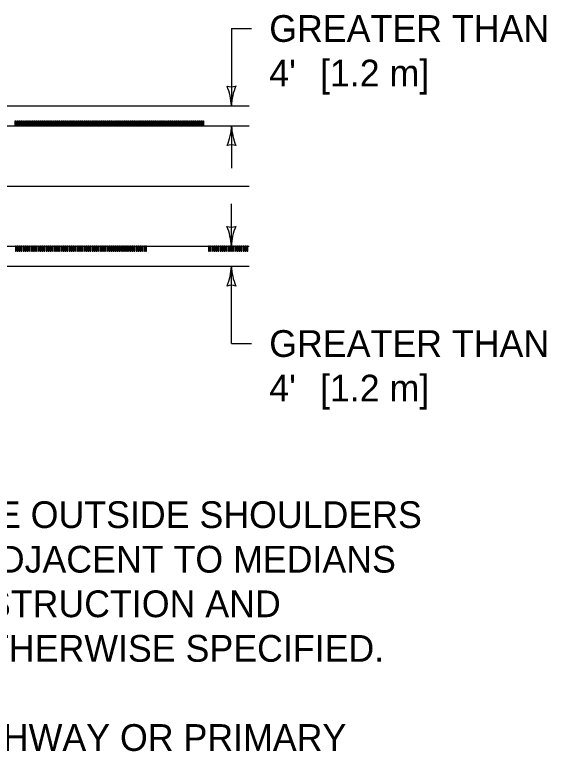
# Model space of a CAD drawing. Extents: x 49991.4 to 50021, y 49987.6 to 50011.4.
# Drawn here: x 50011.188 to 50012.382, y 49993.071 to 49994.724 of the extents above; entities that cross this region are included whole.
import ezdxf

# ---------------------------------------------------------------- set-up
doc = ezdxf.new("R2010")
doc.units = 0
for name, color, linetype in [('Level 1', 7, 'Continuous'), ('Level 2', 7, 'Continuous'), ('Level 3', 7, 'Continuous')]:
    doc.layers.add(name, color=color, linetype=linetype)

msp = doc.modelspace()

# ---------------------------------------------------------------- linework, layer by layer
at = {"layer": 'Level 1'}
for p, q in [((50005.3297, 49994.5195), (50011.7149, 49994.5195)), ((50005.3297, 49994.4745), (50011.7149, 49994.4745)), ((50005.3297, 49994.3395), (50011.7149, 49994.3395)), ((50005.3299, 49994.2045), (50011.7149, 49994.2045)), ((50007.8016, 49994.1595), (50011.7149, 49994.1595))]:
    msp.add_line(p, q, dxfattribs=at)
for points in [[(50011.1912, 49994.4745), (50011.1893, 49994.4745), (50011.1893, 49994.4857), (50011.1912, 49994.4857)], [(50011.1955, 49994.4745), (50011.1936, 49994.4745), (50011.1936, 49994.4857), (50011.1955, 49994.4857)], [(50011.1998, 49994.4745), (50011.1979, 49994.4745), (50011.1979, 49994.4857), (50011.1998, 49994.4857)], [(50011.2041, 49994.4745), (50011.2022, 49994.4745), (50011.2022, 49994.4857), (50011.2041, 49994.4857)], [(50011.2084, 49994.4745), (50011.2065, 49994.4745), (50011.2065, 49994.4857), (50011.2084, 49994.4857)], [(50011.2127, 49994.4745), (50011.2108, 49994.4745), (50011.2108, 49994.4857), (50011.2127, 49994.4857)], [(50011.217, 49994.4745), (50011.2151, 49994.4745), (50011.2151, 49994.4857), (50011.217, 49994.4857)], [(50011.2213, 49994.4745), (50011.2194, 49994.4745), (50011.2194, 49994.4857), (50011.2213, 49994.4857)], [(50011.2256, 49994.4745), (50011.2237, 49994.4745), (50011.2237, 49994.4857), (50011.2256, 49994.4857)], [(50011.2299, 49994.4745), (50011.228, 49994.4745), (50011.228, 49994.4857), (50011.2299, 49994.4857)], [(50011.2342, 49994.4745), (50011.2323, 49994.4745), (50011.2323, 49994.4857), (50011.2342, 49994.4857)], [(50011.2385, 49994.4745), (50011.2366, 49994.4745), (50011.2366, 49994.4857), (50011.2385, 49994.4857)], [(50011.2428, 49994.4745), (50011.2409, 49994.4745), (50011.2409, 49994.4857), (50011.2428, 49994.4857)], [(50011.2471, 49994.4745), (50011.2452, 49994.4745), (50011.2452, 49994.4857), (50011.2471, 49994.4857)], [(50011.2514, 49994.4745), (50011.2495, 49994.4745), (50011.2495, 49994.4857), (50011.2514, 49994.4857)], [(50011.2557, 49994.4745), (50011.2538, 49994.4745), (50011.2538, 49994.4857), (50011.2557, 49994.4857)], [(50011.26, 49994.4745), (50011.2581, 49994.4745), (50011.2581, 49994.4857), (50011.26, 49994.4857)], [(50011.2643, 49994.4745), (50011.2624, 49994.4745), (50011.2624, 49994.4857), (50011.2643, 49994.4857)], [(50011.2686, 49994.4745), (50011.2667, 49994.4745), (50011.2667, 49994.4857), (50011.2686, 49994.4857)], [(50011.2729, 49994.4745), (50011.271, 49994.4745), (50011.271, 49994.4857), (50011.2729, 49994.4857)], [(50011.2772, 49994.4745), (50011.2753, 49994.4745), (50011.2753, 49994.4857), (50011.2772, 49994.4857)], [(50011.2815, 49994.4745), (50011.2796, 49994.4745), (50011.2796, 49994.4857), (50011.2815, 49994.4857)], [(50011.2858, 49994.4745), (50011.2839, 49994.4745), (50011.2839, 49994.4857), (50011.2858, 49994.4857)], [(50011.2901, 49994.4745), (50011.2882, 49994.4745), (50011.2882, 49994.4857), (50011.2901, 49994.4857)], [(50011.2944, 49994.4745), (50011.2925, 49994.4745), (50011.2925, 49994.4857), (50011.2944, 49994.4857)], [(50011.2987, 49994.4745), (50011.2968, 49994.4745), (50011.2968, 49994.4857), (50011.2987, 49994.4857)], [(50011.303, 49994.4745), (50011.3011, 49994.4745), (50011.3011, 49994.4857), (50011.303, 49994.4857)], [(50011.3073, 49994.4745), (50011.3054, 49994.4745), (50011.3054, 49994.4857), (50011.3073, 49994.4857)], [(50011.3116, 49994.4745), (50011.3097, 49994.4745), (50011.3097, 49994.4857), (50011.3116, 49994.4857)], [(50011.3159, 49994.4745), (50011.314, 49994.4745), (50011.314, 49994.4857), (50011.3159, 49994.4857)], [(50011.3202, 49994.4745), (50011.3183, 49994.4745), (50011.3183, 49994.4857), (50011.3202, 49994.4857)], [(50011.3245, 49994.4745), (50011.3226, 49994.4745), (50011.3226, 49994.4857), (50011.3245, 49994.4857)], [(50011.3288, 49994.4745), (50011.3269, 49994.4745), (50011.3269, 49994.4857), (50011.3288, 49994.4857)], [(50011.3331, 49994.4745), (50011.3312, 49994.4745), (50011.3312, 49994.4857), (50011.3331, 49994.4857)], [(50011.3374, 49994.4745), (50011.3355, 49994.4745), (50011.3355, 49994.4857), (50011.3374, 49994.4857)], [(50011.3417, 49994.4745), (50011.3398, 49994.4745), (50011.3398, 49994.4857), (50011.3417, 49994.4857)], [(50011.346, 49994.4745), (50011.3441, 49994.4745), (50011.3441, 49994.4857), (50011.346, 49994.4857)], [(50011.3503, 49994.4745), (50011.3484, 49994.4745), (50011.3484, 49994.4857), (50011.3503, 49994.4857)], [(50011.3546, 49994.4745), (50011.3527, 49994.4745), (50011.3527, 49994.4857), (50011.3546, 49994.4857)], [(50011.3589, 49994.4745), (50011.357, 49994.4745), (50011.357, 49994.4857), (50011.3589, 49994.4857)], [(50011.3632, 49994.4745), (50011.3613, 49994.4745), (50011.3613, 49994.4857), (50011.3632, 49994.4857)], [(50011.3675, 49994.4745), (50011.3656, 49994.4745), (50011.3656, 49994.4857), (50011.3675, 49994.4857)], [(50011.3718, 49994.4745), (50011.3699, 49994.4745), (50011.3699, 49994.4857), (50011.3718, 49994.4857)], [(50011.3761, 49994.4745), (50011.3742, 49994.4745), (50011.3742, 49994.4857), (50011.3761, 49994.4857)], [(50011.3804, 49994.4745), (50011.3785, 49994.4745), (50011.3785, 49994.4857), (50011.3804, 49994.4857)], [(50011.3847, 49994.4745), (50011.3828, 49994.4745), (50011.3828, 49994.4857), (50011.3847, 49994.4857)], [(50011.389, 49994.4745), (50011.3871, 49994.4745), (50011.3871, 49994.4857), (50011.389, 49994.4857)], [(50011.3933, 49994.4745), (50011.3914, 49994.4745), (50011.3914, 49994.4857), (50011.3933, 49994.4857)], [(50011.3976, 49994.4745), (50011.3957, 49994.4745), (50011.3957, 49994.4857), (50011.3976, 49994.4857)], [(50011.4019, 49994.4745), (50011.4, 49994.4745), (50011.4, 49994.4857), (50011.4019, 49994.4857)], [(50011.4062, 49994.4745), (50011.4043, 49994.4745), (50011.4043, 49994.4857), (50011.4062, 49994.4857)], [(50011.4105, 49994.4745), (50011.4086, 49994.4745), (50011.4086, 49994.4857), (50011.4105, 49994.4857)], [(50011.4148, 49994.4745), (50011.4129, 49994.4745), (50011.4129, 49994.4857), (50011.4148, 49994.4857)], [(50011.4191, 49994.4745), (50011.4172, 49994.4745), (50011.4172, 49994.4857), (50011.4191, 49994.4857)], [(50011.4234, 49994.4745), (50011.4215, 49994.4745), (50011.4215, 49994.4857), (50011.4234, 49994.4857)], [(50011.4277, 49994.4745), (50011.4258, 49994.4745), (50011.4258, 49994.4857), (50011.4277, 49994.4857)], [(50011.432, 49994.4745), (50011.4301, 49994.4745), (50011.4301, 49994.4857), (50011.432, 49994.4857)], [(50011.4363, 49994.4745), (50011.4344, 49994.4745), (50011.4344, 49994.4857), (50011.4363, 49994.4857)], [(50011.4406, 49994.4745), (50011.4387, 49994.4745), (50011.4387, 49994.4857), (50011.4406, 49994.4857)], [(50011.4449, 49994.4745), (50011.443, 49994.4745), (50011.443, 49994.4857), (50011.4449, 49994.4857)], [(50011.4492, 49994.4745), (50011.4473, 49994.4745), (50011.4473, 49994.4857), (50011.4492, 49994.4857)], [(50011.4535, 49994.4745), (50011.4516, 49994.4745), (50011.4516, 49994.4857), (50011.4535, 49994.4857)], [(50011.4578, 49994.4745), (50011.4559, 49994.4745), (50011.4559, 49994.4857), (50011.4578, 49994.4857)], [(50011.4621, 49994.4745), (50011.4602, 49994.4745), (50011.4602, 49994.4857), (50011.4621, 49994.4857)], [(50011.4664, 49994.4745), (50011.4645, 49994.4745), (50011.4645, 49994.4857), (50011.4664, 49994.4857)], [(50011.4707, 49994.4745), (50011.4688, 49994.4745), (50011.4688, 49994.4857), (50011.4707, 49994.4857)], [(50011.475, 49994.4745), (50011.4731, 49994.4745), (50011.4731, 49994.4857), (50011.475, 49994.4857)], [(50011.4793, 49994.4745), (50011.4774, 49994.4745), (50011.4774, 49994.4857), (50011.4793, 49994.4857)], [(50011.4836, 49994.4745), (50011.4817, 49994.4745), (50011.4817, 49994.4857), (50011.4836, 49994.4857)], [(50011.4879, 49994.4745), (50011.486, 49994.4745), (50011.486, 49994.4857), (50011.4879, 49994.4857)], [(50011.4922, 49994.4745), (50011.4903, 49994.4745), (50011.4903, 49994.4857), (50011.4922, 49994.4857)], [(50011.4965, 49994.4745), (50011.4946, 49994.4745), (50011.4946, 49994.4857), (50011.4965, 49994.4857)], [(50011.5008, 49994.4745), (50011.4989, 49994.4745), (50011.4989, 49994.4857), (50011.5008, 49994.4857)], [(50011.5051, 49994.4745), (50011.5032, 49994.4745), (50011.5032, 49994.4857), (50011.5051, 49994.4857)], [(50011.5094, 49994.4745), (50011.5075, 49994.4745), (50011.5075, 49994.4857), (50011.5094, 49994.4857)], [(50011.5137, 49994.4745), (50011.5118, 49994.4745), (50011.5118, 49994.4857), (50011.5137, 49994.4857)], [(50011.518, 49994.4745), (50011.5161, 49994.4745), (50011.5161, 49994.4857), (50011.518, 49994.4857)], [(50011.5223, 49994.4745), (50011.5204, 49994.4745), (50011.5204, 49994.4857), (50011.5223, 49994.4857)], [(50011.5266, 49994.4745), (50011.5247, 49994.4745), (50011.5247, 49994.4857), (50011.5266, 49994.4857)], [(50011.5309, 49994.4745), (50011.529, 49994.4745), (50011.529, 49994.4857), (50011.5309, 49994.4857)], [(50011.5352, 49994.4745), (50011.5333, 49994.4745), (50011.5333, 49994.4857), (50011.5352, 49994.4857)], [(50011.5395, 49994.4745), (50011.5376, 49994.4745), (50011.5376, 49994.4857), (50011.5395, 49994.4857)], [(50011.5438, 49994.4745), (50011.5419, 49994.4745), (50011.5419, 49994.4857), (50011.5438, 49994.4857)], [(50011.5481, 49994.4745), (50011.5462, 49994.4745), (50011.5462, 49994.4857), (50011.5481, 49994.4857)], [(50011.5524, 49994.4745), (50011.5505, 49994.4745), (50011.5505, 49994.4857), (50011.5524, 49994.4857)], [(50011.5567, 49994.4745), (50011.5548, 49994.4745), (50011.5548, 49994.4857), (50011.5567, 49994.4857)], [(50011.561, 49994.4745), (50011.5591, 49994.4745), (50011.5591, 49994.4857), (50011.561, 49994.4857)], [(50011.5653, 49994.4745), (50011.5634, 49994.4745), (50011.5634, 49994.4857), (50011.5653, 49994.4857)], [(50011.5696, 49994.4745), (50011.5677, 49994.4745), (50011.5677, 49994.4857), (50011.5696, 49994.4857)], [(50011.5739, 49994.4745), (50011.572, 49994.4745), (50011.572, 49994.4857), (50011.5739, 49994.4857)], [(50011.5782, 49994.4745), (50011.5763, 49994.4745), (50011.5763, 49994.4857), (50011.5782, 49994.4857)], [(50011.5825, 49994.4745), (50011.5806, 49994.4745), (50011.5806, 49994.4857), (50011.5825, 49994.4857)], [(50011.5868, 49994.4745), (50011.5849, 49994.4745), (50011.5849, 49994.4857), (50011.5868, 49994.4857)], [(50011.5911, 49994.4745), (50011.5892, 49994.4745), (50011.5892, 49994.4857), (50011.5911, 49994.4857)], [(50011.5954, 49994.4745), (50011.5935, 49994.4745), (50011.5935, 49994.4857), (50011.5954, 49994.4857)], [(50011.5997, 49994.4745), (50011.5978, 49994.4745), (50011.5978, 49994.4857), (50011.5997, 49994.4857)], [(50011.604, 49994.4745), (50011.6021, 49994.4745), (50011.6021, 49994.4857), (50011.604, 49994.4857)], [(50011.6083, 49994.4745), (50011.6064, 49994.4745), (50011.6064, 49994.4857), (50011.6083, 49994.4857)], [(50011.6126, 49994.4745), (50011.6107, 49994.4745), (50011.6107, 49994.4857), (50011.6126, 49994.4857)], [(50011.1919, 49994.2045), (50011.19, 49994.2045), (50011.19, 49994.1933), (50011.1919, 49994.1933)], [(50011.1962, 49994.2045), (50011.1943, 49994.2045), (50011.1943, 49994.1933), (50011.1962, 49994.1933)], [(50011.2005, 49994.2045), (50011.1986, 49994.2045), (50011.1986, 49994.1933), (50011.2005, 49994.1933)], [(50011.2048, 49994.2045), (50011.2029, 49994.2045), (50011.2029, 49994.1933), (50011.2048, 49994.1933)], [(50011.2091, 49994.2045), (50011.2072, 49994.2045), (50011.2072, 49994.1933), (50011.2091, 49994.1933)], [(50011.2134, 49994.2045), (50011.2115, 49994.2045), (50011.2115, 49994.1933), (50011.2134, 49994.1933)], [(50011.2177, 49994.2045), (50011.2158, 49994.2045), (50011.2158, 49994.1933), (50011.2177, 49994.1933)], [(50011.222, 49994.2045), (50011.2201, 49994.2045), (50011.2201, 49994.1933), (50011.222, 49994.1933)], [(50011.2263, 49994.2045), (50011.2244, 49994.2045), (50011.2244, 49994.1933), (50011.2263, 49994.1933)], [(50011.2306, 49994.2045), (50011.2287, 49994.2045), (50011.2287, 49994.1933), (50011.2306, 49994.1933)], [(50011.2349, 49994.2045), (50011.233, 49994.2045), (50011.233, 49994.1933), (50011.2349, 49994.1933)], [(50011.2392, 49994.2045), (50011.2373, 49994.2045), (50011.2373, 49994.1933), (50011.2392, 49994.1933)], [(50011.2435, 49994.2045), (50011.2416, 49994.2045), (50011.2416, 49994.1933), (50011.2435, 49994.1933)], [(50011.2478, 49994.2045), (50011.2459, 49994.2045), (50011.2459, 49994.1933), (50011.2478, 49994.1933)], [(50011.2521, 49994.2045), (50011.2502, 49994.2045), (50011.2502, 49994.1933), (50011.2521, 49994.1933)], [(50011.2564, 49994.2045), (50011.2545, 49994.2045), (50011.2545, 49994.1933), (50011.2564, 49994.1933)], [(50011.2607, 49994.2045), (50011.2588, 49994.2045), (50011.2588, 49994.1933), (50011.2607, 49994.1933)], [(50011.265, 49994.2045), (50011.2631, 49994.2045), (50011.2631, 49994.1933), (50011.265, 49994.1933)], [(50011.2693, 49994.2045), (50011.2674, 49994.2045), (50011.2674, 49994.1933), (50011.2693, 49994.1933)], [(50011.2736, 49994.2045), (50011.2717, 49994.2045), (50011.2717, 49994.1933), (50011.2736, 49994.1933)], [(50011.2779, 49994.2045), (50011.276, 49994.2045), (50011.276, 49994.1933), (50011.2779, 49994.1933)], [(50011.2822, 49994.2045), (50011.2803, 49994.2045), (50011.2803, 49994.1933), (50011.2822, 49994.1933)], [(50011.2865, 49994.2045), (50011.2846, 49994.2045), (50011.2846, 49994.1933), (50011.2865, 49994.1933)], [(50011.2908, 49994.2045), (50011.2889, 49994.2045), (50011.2889, 49994.1933), (50011.2908, 49994.1933)], [(50011.2951, 49994.2045), (50011.2932, 49994.2045), (50011.2932, 49994.1933), (50011.2951, 49994.1933)], [(50011.2994, 49994.2045), (50011.2975, 49994.2045), (50011.2975, 49994.1933), (50011.2994, 49994.1933)], [(50011.3037, 49994.2045), (50011.3018, 49994.2045), (50011.3018, 49994.1933), (50011.3037, 49994.1933)], [(50011.308, 49994.2045), (50011.3061, 49994.2045), (50011.3061, 49994.1933), (50011.308, 49994.1933)], [(50011.3123, 49994.2045), (50011.3104, 49994.2045), (50011.3104, 49994.1933), (50011.3123, 49994.1933)], [(50011.3166, 49994.2045), (50011.3147, 49994.2045), (50011.3147, 49994.1933), (50011.3166, 49994.1933)], [(50011.3209, 49994.2045), (50011.319, 49994.2045), (50011.319, 49994.1933), (50011.3209, 49994.1933)], [(50011.3252, 49994.2045), (50011.3233, 49994.2045), (50011.3233, 49994.1933), (50011.3252, 49994.1933)], [(50011.3295, 49994.2045), (50011.3276, 49994.2045), (50011.3276, 49994.1933), (50011.3295, 49994.1933)], [(50011.3338, 49994.2045), (50011.3319, 49994.2045), (50011.3319, 49994.1933), (50011.3338, 49994.1933)], [(50011.3381, 49994.2045), (50011.3362, 49994.2045), (50011.3362, 49994.1933), (50011.3381, 49994.1933)], [(50011.3424, 49994.2045), (50011.3405, 49994.2045), (50011.3405, 49994.1933), (50011.3424, 49994.1933)], [(50011.3467, 49994.2045), (50011.3448, 49994.2045), (50011.3448, 49994.1933), (50011.3467, 49994.1933)], [(50011.351, 49994.2045), (50011.3491, 49994.2045), (50011.3491, 49994.1933), (50011.351, 49994.1933)], [(50011.3553, 49994.2045), (50011.3534, 49994.2045), (50011.3534, 49994.1933), (50011.3553, 49994.1933)], [(50011.3596, 49994.2045), (50011.3577, 49994.2045), (50011.3577, 49994.1933), (50011.3596, 49994.1933)], [(50011.3639, 49994.2045), (50011.362, 49994.2045), (50011.362, 49994.1933), (50011.3639, 49994.1933)], [(50011.3682, 49994.2045), (50011.3663, 49994.2045), (50011.3663, 49994.1933), (50011.3682, 49994.1933)], [(50011.3725, 49994.2045), (50011.3706, 49994.2045), (50011.3706, 49994.1933), (50011.3725, 49994.1933)], [(50011.3768, 49994.2045), (50011.3749, 49994.2045), (50011.3749, 49994.1933), (50011.3768, 49994.1933)], [(50011.3811, 49994.2045), (50011.3792, 49994.2045), (50011.3792, 49994.1933), (50011.3811, 49994.1933)], [(50011.3854, 49994.2045), (50011.3835, 49994.2045), (50011.3835, 49994.1933), (50011.3854, 49994.1933)], [(50011.3897, 49994.2045), (50011.3878, 49994.2045), (50011.3878, 49994.1933), (50011.3897, 49994.1933)], [(50011.394, 49994.2045), (50011.3921, 49994.2045), (50011.3921, 49994.1933), (50011.394, 49994.1933)], [(50011.3983, 49994.2045), (50011.3964, 49994.2045), (50011.3964, 49994.1933), (50011.3983, 49994.1933)], [(50011.4026, 49994.2045), (50011.4007, 49994.2045), (50011.4007, 49994.1933), (50011.4026, 49994.1933)], [(50011.4069, 49994.2045), (50011.405, 49994.2045), (50011.405, 49994.1933), (50011.4069, 49994.1933)], [(50011.4112, 49994.2045), (50011.4093, 49994.2045), (50011.4093, 49994.1933), (50011.4112, 49994.1933)], [(50011.4155, 49994.2045), (50011.4136, 49994.2045), (50011.4136, 49994.1933), (50011.4155, 49994.1933)], [(50011.4198, 49994.2045), (50011.4179, 49994.2045), (50011.4179, 49994.1933), (50011.4198, 49994.1933)], [(50011.4241, 49994.2045), (50011.4222, 49994.2045), (50011.4222, 49994.1933), (50011.4241, 49994.1933)], [(50011.4284, 49994.2045), (50011.4265, 49994.2045), (50011.4265, 49994.1933), (50011.4284, 49994.1933)], [(50011.4327, 49994.2045), (50011.4308, 49994.2045), (50011.4308, 49994.1933), (50011.4327, 49994.1933)], [(50011.437, 49994.2045), (50011.4351, 49994.2045), (50011.4351, 49994.1933), (50011.437, 49994.1933)], [(50011.4413, 49994.2045), (50011.4394, 49994.2045), (50011.4394, 49994.1933), (50011.4413, 49994.1933)], [(50011.4456, 49994.2045), (50011.4437, 49994.2045), (50011.4437, 49994.1933), (50011.4456, 49994.1933)], [(50011.4499, 49994.2045), (50011.448, 49994.2045), (50011.448, 49994.1933), (50011.4499, 49994.1933)], [(50011.4542, 49994.2045), (50011.4523, 49994.2045), (50011.4523, 49994.1933), (50011.4542, 49994.1933)], [(50011.4585, 49994.2045), (50011.4566, 49994.2045), (50011.4566, 49994.1933), (50011.4585, 49994.1933)], [(50011.4628, 49994.2045), (50011.4609, 49994.2045), (50011.4609, 49994.1933), (50011.4628, 49994.1933)], [(50011.4671, 49994.2045), (50011.4652, 49994.2045), (50011.4652, 49994.1933), (50011.4671, 49994.1933)], [(50011.4714, 49994.2045), (50011.4695, 49994.2045), (50011.4695, 49994.1933), (50011.4714, 49994.1933)], [(50011.4757, 49994.2045), (50011.4738, 49994.2045), (50011.4738, 49994.1933), (50011.4757, 49994.1933)], [(50011.48, 49994.2045), (50011.4781, 49994.2045), (50011.4781, 49994.1933), (50011.48, 49994.1933)], [(50011.4843, 49994.2045), (50011.4824, 49994.2045), (50011.4824, 49994.1933), (50011.4843, 49994.1933)], [(50011.6255, 49994.2045), (50011.6236, 49994.2045), (50011.6236, 49994.1933), (50011.6255, 49994.1933)], [(50011.6298, 49994.2045), (50011.6279, 49994.2045), (50011.6279, 49994.1933), (50011.6298, 49994.1933)], [(50011.6341, 49994.2045), (50011.6322, 49994.2045), (50011.6322, 49994.1933), (50011.6341, 49994.1933)], [(50011.6384, 49994.2045), (50011.6365, 49994.2045), (50011.6365, 49994.1933), (50011.6384, 49994.1933)], [(50011.6427, 49994.2045), (50011.6408, 49994.2045), (50011.6408, 49994.1933), (50011.6427, 49994.1933)], [(50011.647, 49994.2045), (50011.6451, 49994.2045), (50011.6451, 49994.1933), (50011.647, 49994.1933)], [(50011.6513, 49994.2045), (50011.6494, 49994.2045), (50011.6494, 49994.1933), (50011.6513, 49994.1933)], [(50011.6556, 49994.2045), (50011.6537, 49994.2045), (50011.6537, 49994.1933), (50011.6556, 49994.1933)], [(50011.6599, 49994.2045), (50011.658, 49994.2045), (50011.658, 49994.1933), (50011.6599, 49994.1933)], [(50011.6642, 49994.2045), (50011.6623, 49994.2045), (50011.6623, 49994.1933), (50011.6642, 49994.1933)], [(50011.6685, 49994.2045), (50011.6666, 49994.2045), (50011.6666, 49994.1933), (50011.6685, 49994.1933)], [(50011.6728, 49994.2045), (50011.6709, 49994.2045), (50011.6709, 49994.1933), (50011.6728, 49994.1933)], [(50011.6771, 49994.2045), (50011.6752, 49994.2045), (50011.6752, 49994.1933), (50011.6771, 49994.1933)], [(50011.6814, 49994.2045), (50011.6795, 49994.2045), (50011.6795, 49994.1933), (50011.6814, 49994.1933)], [(50011.6857, 49994.2045), (50011.6838, 49994.2045), (50011.6838, 49994.1933), (50011.6857, 49994.1933)], [(50011.69, 49994.2045), (50011.6881, 49994.2045), (50011.6881, 49994.1933), (50011.69, 49994.1933)], [(50011.6943, 49994.2045), (50011.6924, 49994.2045), (50011.6924, 49994.1933), (50011.6943, 49994.1933)], [(50011.6986, 49994.2045), (50011.6967, 49994.2045), (50011.6967, 49994.1933), (50011.6986, 49994.1933)], [(50011.7029, 49994.2045), (50011.701, 49994.2045), (50011.701, 49994.1933), (50011.7029, 49994.1933)], [(50011.7072, 49994.2045), (50011.7053, 49994.2045), (50011.7053, 49994.1933), (50011.7072, 49994.1933)], [(50011.7115, 49994.2045), (50011.7096, 49994.2045), (50011.7096, 49994.1933), (50011.7115, 49994.1933)]]:
    msp.add_lwpolyline(points, close=True, dxfattribs=at)
at = {"layer": 'Level 3'}
for p, q in [((50011.6749, 49994.6929), (50011.6749, 49994.5195)), ((50011.6749, 49994.6929), (50011.7199, 49994.6929)), ((50011.6752, 49994.4745), (50011.6752, 49994.3794)), ((50011.6748, 49994.2045), (50011.6748, 49994.2994)), ((50011.6749, 49993.9861), (50011.6749, 49994.1595)), ((50011.6749, 49993.9861), (50011.7199, 49993.9861))]:
    msp.add_line(p, q, dxfattribs=at)
for centre, radius, start, end in [((50011.6749, 49994.5943), 0.032, 252.1388, 287.8612), ((50011.5392, 49994.5128), 0.1359, 2.8273, 22.0772), ((50011.8045, 49994.5142), 0.1297, 157.456, 177.6395), ((50011.5456, 49994.4798), 0.1297, 337.456, 357.6395), ((50011.8109, 49994.4812), 0.1359, 182.8273, 202.0772), ((50011.6752, 49994.3997), 0.032, 72.1388, 107.8612), ((50011.6748, 49994.2793), 0.032, 252.1388, 287.8612), ((50011.5391, 49994.1978), 0.1359, 2.8273, 22.0772), ((50011.8044, 49994.1992), 0.1297, 157.456, 177.6395), ((50011.5453, 49994.1648), 0.1297, 337.456, 357.6395), ((50011.8106, 49994.1662), 0.1359, 182.8273, 202.0772), ((50011.6749, 49994.0847), 0.032, 72.1388, 107.8612)]:
    msp.add_arc(centre, radius, start, end, dxfattribs=at)

# ---------------------------------------------------------------- texts
at = {"layer": 'Level 2'}
for s, p in [('GREATER THAN', (50011.7599, 49994.6629)), ("4' ", (50011.7599, 49994.5629)), ('[1.2 m]', (50011.8739, 49994.5629)), ('GREATER THAN', (50011.7599, 49993.9561)), ("4' ", (50011.7599, 49993.8561)), ('[1.2 m] ', (50011.8739, 49993.8561))]:
    msp.add_text(s, height=0.06, rotation=360, dxfattribs=at).set_placement(p)
for s, p in [('PROVIDE RUMBLE STRIPS ON THE OUTSIDE SHOULDERS ', (50009.8467, 49993.5722)), ('(INTERMITTENT PATTERN) AND ADJACENT TO MEDIANS ', (50009.8467, 49993.4722)), ('OF ALL CONSTRUCTION, RECONSTRUCTION AND ', (50009.8467, 49993.3722)), ('OVERLAY PROJECTS, UNLESS OTHERWISE SPECIFIED.', (50009.8467, 49993.2722)), ('ON SEGMENTS OF NATIONAL HIGHWAY OR PRIMARY', (50009.8467, 49993.0722))]:
    msp.add_text(s, height=0.06, dxfattribs=at).set_placement(p)

doc.saveas('drawing.dxf')
